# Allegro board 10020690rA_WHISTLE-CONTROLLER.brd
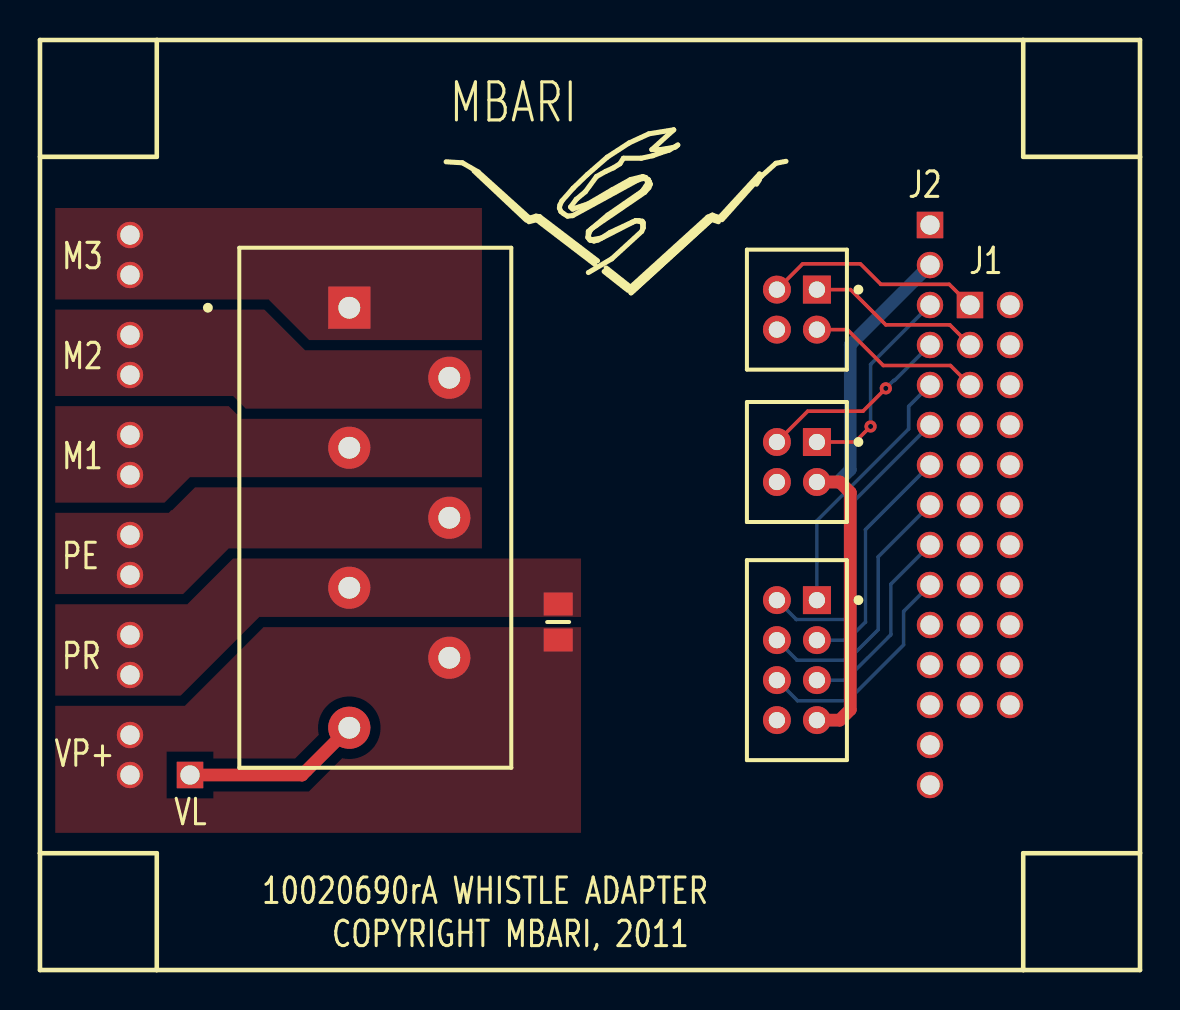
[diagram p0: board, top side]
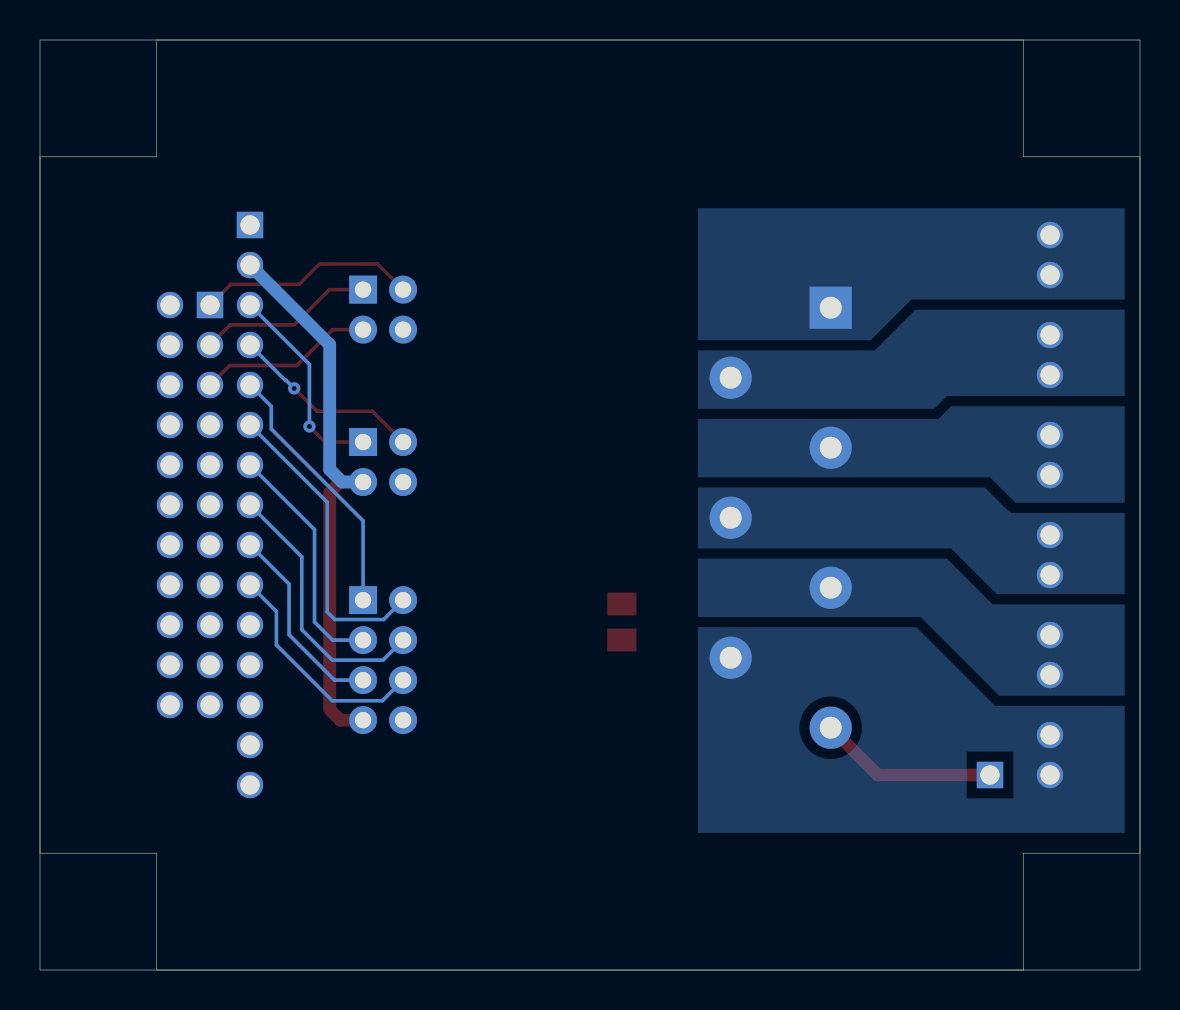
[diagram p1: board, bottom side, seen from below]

Outline 55 x 46.5 mm; copper layers: TOP, BOTTOM. Coordinates in mm from the lower left corner of the outline.
Outline path: 0,46.5 0,0 55,0 55,46.5 0,46.5

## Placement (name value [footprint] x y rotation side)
C1  1.0uF  [CAPC2012X145N]  25.91 17.4 90 top
J3  805-107  [WAGO_805-107]  15.46 33.11 90 top
J4  DF11-8DP-2DSA(01)  [HIROSE_DF11-8DP-2DSA]  38.85 18.49 90 top
J5  DF11-4DP-2DSA(01)  [HIROSE_DF11-4DP-2DSA]  38.85 26.4 90 top
J6  DF11-4DP-2DSA(01)  [HIROSE_DF11-4DP-2DSA]  38.85 34.02 90 top
MOD1  WHI-A15/60R  [ELMO_WHISTLE]  27.5 23.25 0 top
NOREF  -  []  -50.8 -76.2 0 top
NOREF#2  -  []  -50.8 -76.2 0 top
NOREF#3  -  []  144.78 -66.04 0 top
NOREF#4  -  []  256.03 33.78 0 top
NOREF#5  -  []  0 0 0 top
NOREF#6  -  []  0 0 90 top
NOREF#7  -  []  29.53 43.03 0 top

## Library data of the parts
C1 = CAP
J3 = CON7
J4 = CON8
J5 J6 = CON4
MOD1 = ELMO_WHI-Axx/yyyR

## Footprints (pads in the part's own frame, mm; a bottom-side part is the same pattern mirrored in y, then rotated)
CAPC2012X145N
  rect 1.15x1.45 smd: 1(-0.9,0) 2(0.9,0)
ELMO_WHISTLE
  rect 1.321x1.321 hole 0.965: 1(-20,-13.5) J1-1(18.999,10) J2-1(17,14)
  round 1.321 hole 0.965: 2(-23,-13.5) 3(-23,-11.501) 4(-23,-8.499) 5(-23,-6.5) 6(-23,-3.5) 7(-23,-1.501) 8(-23,1.501) 9(-23,3.5) 10(-23,6.5) 11(-23,8.499) 12(-23,11.501) 13(-23,13.5) J1-2(18.999,8.001) J1-3(18.999,5.999) J1-4(18.999,4) J1-5(18.999,1.999) J1-6(18.999,0) J1-7(18.999,-1.999) J1-8(18.999,-4) J1-9(18.999,-5.999) J1-10(18.999,-8.001) J1-11(18.999,-10) J1-12(21.001,10) J1-13(21.001,8.001) J1-14(21.001,5.999) J1-15(21.001,4) J1-16(21.001,1.999) J1-17(21.001,0) J1-18(21.001,-1.999) J1-19(21.001,-4) J1-20(21.001,-5.999) J1-21(21.001,-8.001) J1-22(21.001,-10) J2-2(17,11.999) J2-3(17,10) J2-4(17,8.001) J2-5(17,5.999) J2-6(17,4) J2-7(17,1.999) J2-8(17,0) J2-9(17,-1.999) J2-10(17,-4) J2-11(17,-5.999) J2-12(17,-8.001) J2-13(17,-10) J2-14(17,-11.999) J2-15(17,-14)
HIROSE_DF11-4DP-2DSA
  rect 1.397x1.397 hole 0.813: 1(0,0)
  round 1.397 hole 0.813: 2(0,2) 3(-2,0) 4(-2,2)
HIROSE_DF11-8DP-2DSA
  rect 1.397x1.397 hole 0.813: 1(0,0)
  round 1.397 hole 0.813: 2(0,2) 3(-2,0) 4(-2,2) 5(-4,0) 6(-4,2) 7(-6,0) 8(-6,2)
WAGO_805-107
  rect 2.108x2.108 hole 1.092: 1(0,0)
  round 2.108 hole 1.092: 2(-3.5,-5.001) 3(-7,0) 4(-10.5,-5.001) 5(-14,0) 6(-17.501,-5.001) 7(-21.001,0)

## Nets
M1: J3.3 MOD1.8(M1_1) MOD1.9(M1_2)
M2: J3.2 MOD1.10(M2_1) MOD1.11(M2_2)
M3: J3.1 MOD1.12(M3_1) MOD1.13(M3_2)
PE: J3.4 MOD1.6(PE_1) MOD1.7(PE_2)
PR: C1.2 J3.5 MOD1.4(PR_1) MOD1.5(PR_2)
VL: J3.7 MOD1.1(VL)
VP: C1.1 J3.6 MOD1.2(VP+_1) MOD1.3(VP+_2)
N00583: J4.1 MOD1.J2-5(CHA)
N00587: J4.2 MOD1.J2-6(CHA-)
N00591: J4.3 MOD1.J2-7(CHB)
N00606: J4.4 MOD1.J2-8(CHB-)
N00618: J4.5 MOD1.J2-9(INDEX/VREF)
N00631: J4.6 MOD1.J2-10(INDEX-/VREF-)
N00643: J4.7 J5.3 MOD1.J2-2(SUPRET/ANLRET)
N01292: J6.1 MOD1.J1-2(RS232_TX)
N01296: J6.2 MOD1.J1-1(RS232_RX)
N01300: J6.3 MOD1.J1-3(RS232_COMRET)
N02903: J5.1 MOD1.J2-3(ANALIN+)
N02905: J5.2 MOD1.J2-4(ANALIN-)

Pads without a net: J4 8; J5 4; J6 4; MOD1 J1-4 J1-5 J1-6 J1-7 J1-8 J1-9 J1-10 J1-11 J1-12 J1-13 J1-14 J1-15 J1-16 J1-17 J1-18 J1-19 J1-20 J1-21 J1-22 J2-1 J2-11 J2-12 J2-13 J2-14 J2-15

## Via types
v1: diameter 0.61, hole 0.254, TOP to BOTTOM, 2 vias

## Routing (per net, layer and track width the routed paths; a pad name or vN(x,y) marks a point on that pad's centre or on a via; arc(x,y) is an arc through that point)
VL: length 8.9
  TOP w0.635: J3.7 13.1,9.75 MOD1.1
N00583: length 13.1
  BOTTOM w0.178: MOD1.J2-5 43.43,28.18 43.43,27.05 38.85,22.46 J4.1
N00587: length 15.3
  BOTTOM w0.178: MOD1.J2-6 40.64,23.39 40.64,17.91 40.26,17.53 37.81,17.53 J4.2
N00591: length 12
  BOTTOM w0.178: MOD1.J2-7 41.27,22.02 41.27,17.4 40.37,16.49 J4.3
N00606: length 13.4
  BOTTOM w0.178: MOD1.J2-8 41.91,20.66 41.91,17.02 40.39,15.49 37.85,15.49 J4.4
N00618: length 9.9
  BOTTOM w0.178: J4.5 40.28,14.49 42.55,16.76 42.55,19.3 MOD1.J2-9
N00631: length 11.5
  BOTTOM w0.178: J4.6 37.88,13.46 40.39,13.46 43.18,16.26 43.18,17.93 MOD1.J2-10
N00643: length 28.4
  TOP w0.635: J5.3 39.99,24.4 40.51,23.88 40.51,13.02 39.99,12.49 J4.7
  BOTTOM w0.635: MOD1.J2-2 40.51,31.26 40.51,25.02 39.89,24.4 J5.3
N01292: length 8.8
  TOP w0.178: J6.1 40.53,34.02 42.29,32.26 45.49,32.26 MOD1.J1-2
N01296: length 11
  TOP w0.178: J6.2 38.13,35.31 41.02,35.31 42.04,34.28 45.47,34.28 MOD1.J1-1
N01300: length 8.8
  TOP w0.178: MOD1.J1-3 45.52,30.23 42.16,30.23 40.37,32.02 J6.3
N02903: length 10.3
  TOP w0.178: J5.1 40.75,26.4 v1(41.53,27.18)
  BOTTOM w0.178: MOD1.J2-3 41.53,30.28 v1(41.53,27.18)
N02905: length 9.7
  TOP w0.178: J5.2 38.39,27.94 41.15,27.94 v1(42.29,29.08)
  BOTTOM w0.178: v1(42.29,29.08) 42.69,29.48 42.73,29.48 MOD1.J2-4

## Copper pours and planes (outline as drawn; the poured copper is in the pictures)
M1 on TOP: 0.76,28.19 9.53,28.19 10.03,27.69 22.1,27.69 22.1,24.64 7.49,24.64 6.22,23.37 0.76,23.37
M1 on BOTTOM: 0.76,28.19 9.53,28.19 10.03,27.68 22.1,27.68 22.1,24.63 7.49,24.63 6.22,23.36 0.76,23.36
M2 on TOP: 0.76,33.02 11.3,33.02 13.21,31.11 22.1,31.11 22.1,28.07 10.29,28.07 9.65,28.7 0.76,28.7
M2 on BOTTOM: 0.76,33.01 11.3,33.01 13.21,31.11 22.1,31.11 22.1,28.06 10.29,28.06 9.65,28.7 0.76,28.7
M3 on TOP: 0.76,38.1 22.1,38.1 22.1,31.5 13.46,31.5 11.43,33.53 0.76,33.53
M3 on BOTTOM: 0.76,38.09 22.1,38.09 22.1,31.49 13.46,31.49 11.43,33.52 0.76,33.52
PE on TOP: 0.76,22.99 6.6,22.99 7.87,24.26 22.1,24.26 22.1,20.95 9.4,20.95 7.11,18.67 0.76,18.67
PE on BOTTOM: 0.76,22.98 6.61,22.98 7.88,24.25 22.1,24.25 22.1,20.95 9.4,20.95 7.11,18.66 0.76,18.66
PR on TOP: 0.76,18.29 7.37,18.29 9.65,20.57 27.05,20.57 27.05,17.53 10.92,17.53 6.99,13.59 0.76,13.59
PR on BOTTOM: 0.76,18.28 7.37,18.28 9.65,20.57 22.1,20.57 22.1,17.52 10.92,17.52 6.99,13.58 0.76,13.58
VP on TOP: 0.76,13.21 7.24,13.21 11.18,17.14 27.05,17.14 27.05,6.86 0.76,6.86
VP on BOTTOM: 0.76,13.2 7.24,13.2 11.18,17.14 22.1,17.14 22.1,6.85 0.76,6.85

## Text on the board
User.Comments: *POWER TRACES ARE ROUGHLY RATED TO 18AMPS WITH A TEMPERATURE RISE | OF 20 DEGREES CELCIUS IN AIR.  RUNNING TEMPERATURE IN OIL SHOULD BE LOWER.
Ref Des/Silkscreen Top: 10020690rA WHISTLE ADAPTER | COPYRIGHT MBARI, 2011
User.6: FIGURE | SIZE | 10.0 | 32.0 | 38.0 | 43.0 | DRILL CHART: TOP to BOTTOM | ALL UNITS ARE IN MILS | PLATED | QTY | 2 | 16 | 50 | 7
